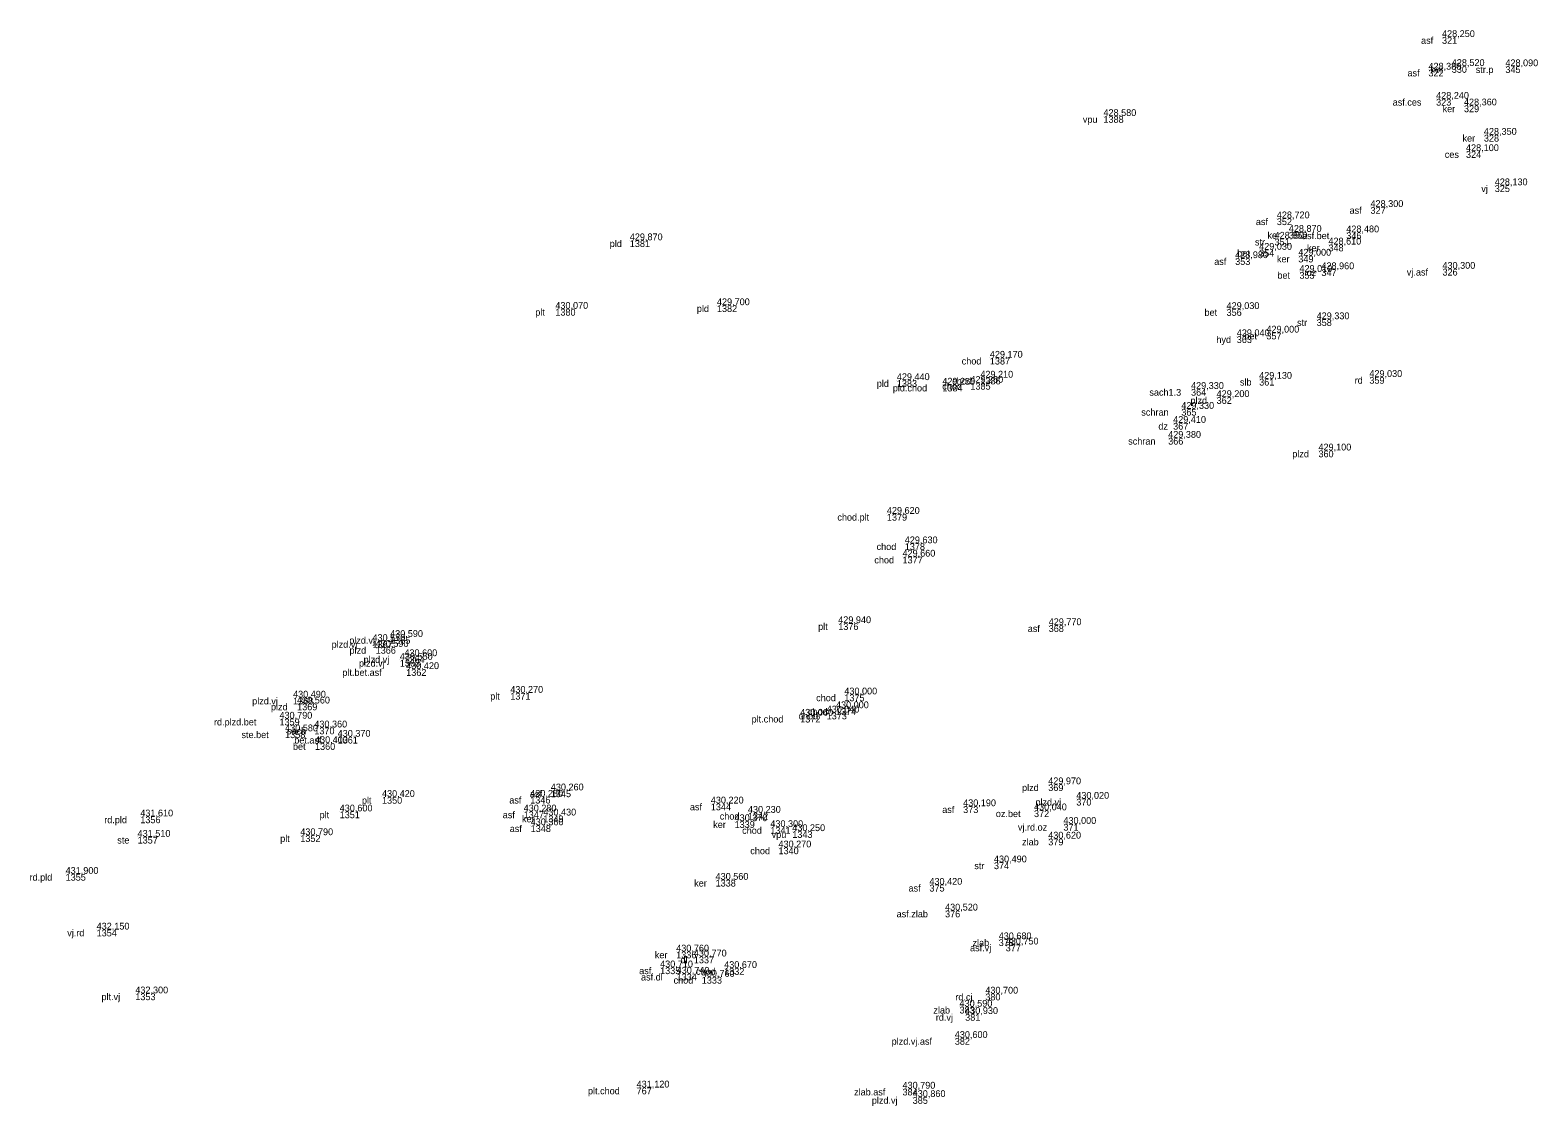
# Model space of a CAD drawing. Extents: x -747136 to -746138, y -1093274 to -1091717.
# Drawn here: x -746656.1 to -746589.5, y -1092982.2 to -1092934.6 of the extents above; entities that cross this region are included whole.
import ezdxf

# ---------------------------------------------------------------- set-up
doc = ezdxf.new("R2010")
doc.units = 0
for name, color, linetype in [('1029', 7, 'Continuous'), ('404', 7, 'Continuous'), ('424', 7, 'Continuous')]:
    doc.layers.add(name, color=color, linetype=linetype)

msp = doc.modelspace()

# ---------------------------------------------------------------- linework, layer by layer
at = {"layer": '404'}
for p, q in [((-746593.72, -1092934.95), (-746593.72, -1092934.95)), ((-746593.29, -1092936.23), (-746593.29, -1092936.23)), ((-746590.92, -1092936.24), (-746590.92, -1092936.24)), ((-746594.32, -1092936.39), (-746594.32, -1092936.39)), ((-746593.98, -1092937.68), (-746593.98, -1092937.68)), ((-746592.75, -1092937.97), (-746592.75, -1092937.97)), ((-746608.68, -1092938.44), (-746608.68, -1092938.44)), ((-746591.87, -1092939.27), (-746591.87, -1092939.27)), ((-746592.66, -1092939.99), (-746592.66, -1092939.99)), ((-746591.39, -1092941.5), (-746591.39, -1092941.5)), ((-746601.02, -1092942.96), (-746601.02, -1092942.96)), ((-746596.88, -1092942.46), (-746596.88, -1092942.46)), ((-746600.49, -1092943.56), (-746600.49, -1092943.56)), ((-746597.95, -1092943.58), (-746597.95, -1092943.58)), ((-746629.61, -1092943.93), (-746629.61, -1092943.93)), ((-746601.8, -1092944.35), (-746601.8, -1092944.35)), ((-746601.12, -1092943.86), (-746601.12, -1092943.86)), ((-746598.74, -1092944.12), (-746598.74, -1092944.12)), ((-746602.86, -1092944.72), (-746602.86, -1092944.72)), ((-746600.07, -1092944.61), (-746600.07, -1092944.61)), ((-746600.02, -1092945.33), (-746600.02, -1092945.33)), ((-746599.05, -1092945.21), (-746599.05, -1092945.21)), ((-746593.7, -1092945.19), (-746593.7, -1092945.19)), ((-746632.9, -1092946.96), (-746632.9, -1092946.96)), ((-746625.76, -1092946.8), (-746625.76, -1092946.8)), ((-746603.24, -1092946.97), (-746603.24, -1092946.97)), ((-746599.26, -1092947.42), (-746599.26, -1092947.42)), ((-746602.79, -1092948.17), (-746602.79, -1092948.17)), ((-746601.48, -1092948.01), (-746601.48, -1092948.01)), ((-746613.7, -1092949.12), (-746613.7, -1092949.12)), ((-746617.81, -1092950.11), (-746617.81, -1092950.11)), ((-746615.8, -1092950.31), (-746615.8, -1092950.31)), ((-746614.56, -1092950.23), (-746614.56, -1092950.23)), ((-746614.12, -1092950), (-746614.12, -1092950)), ((-746601.8, -1092950.05), (-746601.8, -1092950.05)), ((-746596.93, -1092949.97), (-746596.93, -1092949.97)), ((-746604.81, -1092950.5), (-746604.81, -1092950.5)), ((-746603.68, -1092950.86), (-746603.68, -1092950.86)), ((-746605.24, -1092951.38), (-746605.24, -1092951.38)), ((-746605.6, -1092952), (-746605.6, -1092952)), ((-746605.82, -1092952.66), (-746605.82, -1092952.66)), ((-746599.18, -1092953.22), (-746599.18, -1092953.22)), ((-746618.25, -1092956.02), (-746618.25, -1092956.02)), ((-746617.46, -1092957.32), (-746617.46, -1092957.32)), ((-746617.56, -1092957.91), (-746617.56, -1092957.91)), ((-746620.4, -1092960.85), (-746620.4, -1092960.85)), ((-746611.1, -1092960.94), (-746611.1, -1092960.94)), ((-746640.98, -1092961.64), (-746640.98, -1092961.64)), ((-746640.2, -1092961.46), (-746640.2, -1092961.46)), ((-746640.84, -1092961.9), (-746640.84, -1092961.9)), ((-746639.57, -1092962.31), (-746639.57, -1092962.31)), ((-746639.77, -1092962.47), (-746639.77, -1092962.47)), ((-746639.49, -1092962.88), (-746639.49, -1092962.88)), ((-746644.49, -1092964.14), (-746644.49, -1092964.14)), ((-746634.89, -1092963.93), (-746634.89, -1092963.93)), ((-746620.13, -1092964), (-746620.13, -1092964)), ((-746644.31, -1092964.4), (-746644.31, -1092964.4)), ((-746622.08, -1092964.94), (-746622.08, -1092964.94)), ((-746620.91, -1092964.8), (-746620.91, -1092964.8)), ((-746620.5, -1092964.61), (-746620.5, -1092964.61)), ((-746645.09, -1092965.07), (-746645.09, -1092965.07)), ((-746644.84, -1092965.63), (-746644.84, -1092965.63)), ((-746643.55, -1092965.46), (-746643.55, -1092965.46)), ((-746643.52, -1092966.15), (-746643.52, -1092966.15)), ((-746642.52, -1092965.87), (-746642.52, -1092965.87)), ((-746633.1, -1092968.24), (-746633.1, -1092968.24)), ((-746611.12, -1092967.97), (-746611.12, -1092967.97)), ((-746640.56, -1092968.53), (-746640.56, -1092968.53)), ((-746634.01, -1092968.52), (-746634.01, -1092968.52)), ((-746626.03, -1092968.82), (-746626.03, -1092968.82)), ((-746614.88, -1092968.94), (-746614.88, -1092968.94)), ((-746609.88, -1092968.61), (-746609.88, -1092968.61)), ((-746651.24, -1092969.39), (-746651.24, -1092969.39)), ((-746642.43, -1092969.17), (-746642.43, -1092969.17)), ((-746634.3, -1092969.17), (-746634.3, -1092969.17)), ((-746633.43, -1092969.35), (-746633.43, -1092969.35)), ((-746624.98, -1092969.6), (-746624.98, -1092969.6)), ((-746624.39, -1092969.23), (-746624.39, -1092969.23)), ((-746611.75, -1092969.12), (-746611.75, -1092969.12)), ((-746651.36, -1092970.29), (-746651.36, -1092970.29)), ((-746644.17, -1092970.22), (-746644.17, -1092970.22)), ((-746633.99, -1092969.78), (-746633.99, -1092969.78)), ((-746623.4, -1092969.86), (-746623.4, -1092969.86)), ((-746622.43, -1092970.04), (-746622.43, -1092970.04)), ((-746610.45, -1092969.72), (-746610.45, -1092969.72)), ((-746623.04, -1092970.76), (-746623.04, -1092970.76)), ((-746611.12, -1092970.37), (-746611.12, -1092970.37)), ((-746613.52, -1092971.42), (-746613.52, -1092971.42)), ((-746654.54, -1092971.93), (-746654.54, -1092971.93)), ((-746625.82, -1092972.19), (-746625.82, -1092972.19)), ((-746616.37, -1092972.41), (-746616.37, -1092972.41)), ((-746615.68, -1092973.55), (-746615.68, -1092973.55)), ((-746653.17, -1092974.39), (-746653.17, -1092974.39)), ((-746613.31, -1092974.82), (-746613.31, -1092974.82)), ((-746627.56, -1092975.36), (-746627.56, -1092975.36)), ((-746626.78, -1092975.58), (-746626.78, -1092975.58)), ((-746613, -1092975.05), (-746613, -1092975.05)), ((-746628.27, -1092976.06), (-746628.27, -1092976.06)), ((-746627.54, -1092976.34), (-746627.54, -1092976.34)), ((-746625.44, -1092976.09), (-746625.44, -1092976.09)), ((-746626.43, -1092976.48), (-746626.43, -1092976.48)), ((-746651.46, -1092977.21), (-746651.46, -1092977.21)), ((-746613.9, -1092977.22), (-746613.9, -1092977.22)), ((-746615.04, -1092977.8), (-746615.04, -1092977.8)), ((-746614.79, -1092978.12), (-746614.79, -1092978.12)), ((-746615.25, -1092979.18), (-746615.25, -1092979.18)), ((-746629.31, -1092981.37), (-746629.31, -1092981.37)), ((-746617.56, -1092981.42), (-746617.56, -1092981.42)), ((-746617.11, -1092981.79), (-746617.11, -1092981.79))]:
    msp.add_line(p, q, dxfattribs=at)

# ---------------------------------------------------------------- texts
at = {"layer": '1029'}
for s, p in [('428,250', (-746593.72, -1092934.95)), ('428,380', (-746594.32, -1092936.39)), ('428,520', (-746593.29, -1092936.23)), ('428,090', (-746590.92, -1092936.24)), ('428,240', (-746593.98, -1092937.68)), ('428,360', (-746592.75, -1092937.97)), ('428,580', (-746608.68, -1092938.44)), ('428,350', (-746591.87, -1092939.27)), ('428,100', (-746592.66, -1092939.99)), ('428,130', (-746591.39, -1092941.5)), ('428,300', (-746596.88, -1092942.46)), ('428,720', (-746601.02, -1092942.96)), ('429,870', (-746629.61, -1092943.93)), ('428,950', (-746601.12, -1092943.86)), ('428,870', (-746600.49, -1092943.56)), ('428,480', (-746597.95, -1092943.58)), ('429,030', (-746601.8, -1092944.35)), ('429,000', (-746600.07, -1092944.61)), ('428,610', (-746598.74, -1092944.12)), ('428,980', (-746602.86, -1092944.72)), ('429,010', (-746600.02, -1092945.33)), ('428,960', (-746599.05, -1092945.21)), ('430,300', (-746593.7, -1092945.19)), ('430,070', (-746632.9, -1092946.96)), ('429,700', (-746625.76, -1092946.8)), ('429,030', (-746603.24, -1092946.97)), ('429,000', (-746601.48, -1092948.01)), ('429,330', (-746599.26, -1092947.42)), ('429,040', (-746602.79, -1092948.17)), ('429,170', (-746613.7, -1092949.12)), ('429,210', (-746614.12, -1092950)), ('429,030', (-746596.93, -1092949.97)), ('429,440', (-746617.81, -1092950.11)), ('429,250', (-746615.8, -1092950.31)), ('429,260', (-746614.56, -1092950.23)), ('429,330', (-746604.81, -1092950.5)), ('429,130', (-746601.8, -1092950.05)), ('429,200', (-746603.68, -1092950.86)), ('429,410', (-746605.6, -1092952)), ('429,330', (-746605.24, -1092951.38)), ('429,380', (-746605.82, -1092952.66)), ('429,100', (-746599.18, -1092953.22)), ('429,620', (-746618.25, -1092956.02)), ('429,630', (-746617.46, -1092957.32)), ('429,660', (-746617.56, -1092957.91)), ('429,940', (-746620.4, -1092960.85)), ('429,770', (-746611.1, -1092960.94)), ('430,570', (-746640.98, -1092961.64)), ('430,590', (-746640.84, -1092961.9)), ('430,590', (-746640.2, -1092961.46)), ('430,550', (-746639.77, -1092962.47)), ('430,600', (-746639.57, -1092962.31)), ('430,420', (-746639.49, -1092962.88)), ('430,270', (-746634.89, -1092963.93)), ('430,000', (-746620.13, -1092964)), ('430,490', (-746644.49, -1092964.14)), ('430,560', (-746644.31, -1092964.4)), ('430,000', (-746620.5, -1092964.61)), ('430,790', (-746645.09, -1092965.07)), ('430,060', (-746622.08, -1092964.94)), ('430,040', (-746620.91, -1092964.8)), ('430,580', (-746644.84, -1092965.63)), ('430,360', (-746643.55, -1092965.46)), ('430,370', (-746642.52, -1092965.87)), ('430,400', (-746643.52, -1092966.15)), ('429,970', (-746611.12, -1092967.97)), ('430,420', (-746640.56, -1092968.53)), ('430,280', (-746634.01, -1092968.52)), ('430,260', (-746633.1, -1092968.24)), ('430,020', (-746609.88, -1092968.61)), ('430,600', (-746642.43, -1092969.17)), ('430,280', (-746634.3, -1092969.17)), ('430,220', (-746626.03, -1092968.82)), ('430,230', (-746624.39, -1092969.23)), ('430,190', (-746614.88, -1092968.94)), ('430,040', (-746611.75, -1092969.12)), ('431,610', (-746651.24, -1092969.39)), ('430,360', (-746633.99, -1092969.78)), ('430,430', (-746633.43, -1092969.35)), ('430,370', (-746624.98, -1092969.6)), ('430,300', (-746623.4, -1092969.86)), ('430,000', (-746610.45, -1092969.72)), ('431,510', (-746651.36, -1092970.29)), ('430,790', (-746644.17, -1092970.22)), ('430,250', (-746622.43, -1092970.04)), ('430,620', (-746611.12, -1092970.37)), ('430,270', (-746623.04, -1092970.76)), ('431,900', (-746654.54, -1092971.93)), ('430,490', (-746613.52, -1092971.42)), ('430,560', (-746625.82, -1092972.19)), ('430,420', (-746616.37, -1092972.41)), ('430,520', (-746615.68, -1092973.55)), ('432,150', (-746653.17, -1092974.39)), ('430,680', (-746613.31, -1092974.82)), ('430,750', (-746613, -1092975.05)), ('430,760', (-746627.56, -1092975.36)), ('430,770', (-746626.78, -1092975.58)), ('430,710', (-746628.27, -1092976.06)), ('430,740', (-746627.54, -1092976.34)), ('430,760', (-746626.43, -1092976.48)), ('430,670', (-746625.44, -1092976.09)), ('432,300', (-746651.46, -1092977.21)), ('430,700', (-746613.9, -1092977.22)), ('430,590', (-746615.04, -1092977.8)), ('430,930', (-746614.79, -1092978.12)), ('430,600', (-746615.25, -1092979.18)), ('431,120', (-746629.31, -1092981.37)), ('430,790', (-746617.56, -1092981.42)), ('430,860', (-746617.11, -1092981.79))]:
    msp.add_text(s, height=0.3, dxfattribs=at).set_placement(p)
at = {"layer": '424'}
for s, p in [(' asf', (-746594.757, -1092935.25)), ('321', (-746593.72, -1092935.25)), (' asf', (-746595.357, -1092936.69)), (' ker', (-746594.346, -1092936.53)), ('330', (-746593.29, -1092936.53)), (' str.p', (-746592.339, -1092936.54)), ('345', (-746590.92, -1092936.54)), ('322', (-746594.32, -1092936.69)), (' asf.ces', (-746596.011, -1092937.98)), ('323', (-746593.98, -1092937.98)), (' ker', (-746593.806, -1092938.27)), ('329', (-746592.75, -1092938.27)), (' vpu', (-746609.703, -1092938.74)), ('1388', (-746608.68, -1092938.74)), (' ker', (-746592.926, -1092939.57)), ('328', (-746591.87, -1092939.57)), (' ces', (-746593.709, -1092940.29)), ('324', (-746592.66, -1092940.29)), (' vj', (-746592.094, -1092941.8)), ('325', (-746591.39, -1092941.8)), (' asf', (-746602.057, -1092943.26)), ('352', (-746601.02, -1092943.26)), (' asf', (-746597.917, -1092942.76)), ('327', (-746596.88, -1092942.76)), (' ker', (-746601.546, -1092943.86)), ('350', (-746600.49, -1092943.86)), (' asf.bet', (-746600.019, -1092943.88)), ('346', (-746597.95, -1092943.88)), (' pld', (-746630.609, -1092944.23)), ('1381', (-746629.61, -1092944.23)), (' bet', (-746602.886, -1092944.65)), (' str', (-746602.098, -1092944.16)), ('354', (-746601.8, -1092944.65)), ('351', (-746601.12, -1092944.16)), (' ker', (-746599.796, -1092944.42)), ('348', (-746598.74, -1092944.42)), (' asf', (-746603.897, -1092945.02)), ('353', (-746602.86, -1092945.02)), (' ker', (-746601.126, -1092944.91)), ('349', (-746600.07, -1092944.91)), (' bet', (-746601.106, -1092945.63)), ('355', (-746600.02, -1092945.63)), (' oz', (-746599.815, -1092945.51)), ('347', (-746599.05, -1092945.51)), (' vj.asf', (-746595.386, -1092945.49)), ('326', (-746593.7, -1092945.49)), (' plt', (-746633.899, -1092947.26)), ('1380', (-746632.9, -1092947.26)), (' pld', (-746626.759, -1092947.1)), ('1382', (-746625.76, -1092947.1)), (' bet', (-746604.326, -1092947.27)), ('356', (-746603.24, -1092947.27)), (' str', (-746600.238, -1092947.72)), ('358', (-746599.26, -1092947.72)), (' hyd', (-746603.801, -1092948.47)), ('363', (-746602.79, -1092948.47)), (' bet', (-746602.566, -1092948.31)), ('357', (-746601.48, -1092948.31)), (' chod', (-746615.056, -1092949.42)), ('1387', (-746613.7, -1092949.42)), (' pld', (-746618.809, -1092950.41)), (' pld.chod', (-746618.1, -1092950.61)), ('1383', (-746617.81, -1092950.41)), (' chod', (-746615.916, -1092950.53)), ('1384', (-746615.8, -1092950.61)), (' chod', (-746615.476, -1092950.3)), ('1385', (-746614.56, -1092950.53)), ('1386', (-746614.12, -1092950.3)), (' slb', (-746602.761, -1092950.35)), ('361', (-746601.8, -1092950.35)), (' rd', (-746597.691, -1092950.27)), ('359', (-746596.93, -1092950.27)), (' sach1.3', (-746606.763, -1092950.8)), (' plzd', (-746604.948, -1092951.16)), ('364', (-746604.81, -1092950.8)), ('362', (-746603.68, -1092951.16)), (' schran', (-746607.118, -1092951.68)), ('365', (-746605.24, -1092951.68)), (' dz', (-746606.365, -1092952.3)), ('367', (-746605.6, -1092952.3)), (' schran', (-746607.698, -1092952.96)), ('366', (-746605.82, -1092952.96)), (' plzd', (-746600.448, -1092953.52)), ('360', (-746599.18, -1092953.52)), (' chod.plt', (-746620.55, -1092956.32)), ('1379', (-746618.25, -1092956.32)), (' chod', (-746618.816, -1092957.62)), ('1378', (-746617.46, -1092957.62)), (' chod', (-746618.916, -1092958.21)), ('1377', (-746617.56, -1092958.21)), (' plt', (-746621.399, -1092961.15)), ('1376', (-746620.4, -1092961.15)), (' asf', (-746612.137, -1092961.24)), ('368', (-746611.1, -1092961.24)), (' plzd.vj', (-746642.898, -1092961.94)), (' plzd.vj', (-746642.118, -1092961.76)), ('1367', (-746640.98, -1092961.94)), ('1365', (-746640.2, -1092961.76)), (' plzd', (-746642.108, -1092962.2)), (' plzd.vj', (-746641.488, -1092962.61)), ('1366', (-746640.84, -1092962.2)), ('1364', (-746639.57, -1092962.61)), (' plt.bet.asf', (-746642.423, -1092963.18)), (' plzd.vj', (-746641.688, -1092962.77)), ('1363', (-746639.77, -1092962.77)), ('1362', (-746639.49, -1092963.18)), (' plzd.vj', (-746646.408, -1092964.44)), ('1368', (-746644.49, -1092964.44)), (' plt', (-746635.889, -1092964.23)), ('1371', (-746634.89, -1092964.23)), (' chod', (-746621.486, -1092964.3)), ('1375', (-746620.13, -1092964.3)), (' plzd', (-746645.578, -1092964.7)), ('1369', (-746644.31, -1092964.7)), (' plt.chod', (-746624.34, -1092965.24)), (' chod', (-746622.266, -1092965.1)), ('1372', (-746622.08, -1092965.24)), (' chod', (-746621.856, -1092964.91)), ('1373', (-746620.91, -1092965.1)), ('1374', (-746620.5, -1092964.91)), (' rd.plzd.bet', (-746648.096, -1092965.37)), (' ste.bet', (-746646.881, -1092965.93)), ('1359', (-746645.09, -1092965.37)), ('1358', (-746644.84, -1092965.93)), (' sach', (-746644.868, -1092965.76)), ('1370', (-746643.55, -1092965.76)), (' bet', (-746644.606, -1092966.45)), (' bet.asf', (-746644.549, -1092966.17)), ('1360', (-746643.52, -1092966.45)), ('1361', (-746642.52, -1092966.17)), (' asf', (-746634.137, -1092968.54)), ('1345', (-746633.1, -1092968.54)), (' plzd', (-746612.388, -1092968.27)), ('369', (-746611.12, -1092968.27)), (' plt', (-746641.559, -1092968.83)), ('1350', (-746640.56, -1092968.83)), (' asf', (-746635.047, -1092968.82)), ('1346', (-746634.01, -1092968.82)), (' asf', (-746627.067, -1092969.12)), ('1344', (-746626.03, -1092969.12)), (' asf', (-746615.917, -1092969.24)), ('373', (-746614.88, -1092969.24)), (' plzd.vj', (-746611.798, -1092968.91)), ('370', (-746609.88, -1092968.91)), (' rd.pld', (-746652.945, -1092969.69)), ('1356', (-746651.24, -1092969.69)), (' plt', (-746643.429, -1092969.47)), ('1351', (-746642.43, -1092969.47)), (' asf', (-746635.337, -1092969.47)), (' ker', (-746634.486, -1092969.65)), ('1347', (-746634.3, -1092969.47)), ('1349', (-746633.43, -1092969.65)), (' ker', (-746626.036, -1092969.9)), (' chod', (-746625.746, -1092969.53)), ('1339', (-746624.98, -1092969.9)), ('1342', (-746624.39, -1092969.53)), (' oz.bet', (-746613.547, -1092969.42)), ('372', (-746611.75, -1092969.42)), (' ste', (-746652.369, -1092970.59)), ('1357', (-746651.36, -1092970.59)), (' plt', (-746645.169, -1092970.52)), ('1352', (-746644.17, -1092970.52)), (' asf', (-746635.027, -1092970.08)), ('1348', (-746633.99, -1092970.08)), (' chod', (-746624.756, -1092970.16)), ('1341', (-746623.4, -1092970.16)), (' vpu', (-746623.453, -1092970.34)), ('1343', (-746622.43, -1092970.34)), (' vj.rd.oz', (-746612.571, -1092970.02)), (' zlab', (-746612.388, -1092970.67)), ('371', (-746610.45, -1092970.02)), (' chod', (-746624.396, -1092971.06)), ('1340', (-746623.04, -1092971.06)), ('379', (-746611.12, -1092970.67)), (' str', (-746614.498, -1092971.72)), ('374', (-746613.52, -1092971.72)), (' rd.pld', (-746656.245, -1092972.23)), ('1355', (-746654.54, -1092972.23)), (' ker', (-746626.876, -1092972.49)), ('1338', (-746625.82, -1092972.49)), (' asf', (-746617.407, -1092972.71)), ('375', (-746616.37, -1092972.71)), (' asf.zlab', (-746617.931, -1092973.85)), ('376', (-746615.68, -1092973.85)), (' vj.rd', (-746654.58, -1092974.69)), ('1354', (-746653.17, -1092974.69)), (' zlab', (-746614.578, -1092975.12)), ('378', (-746613.31, -1092975.12)), (' ker', (-746628.616, -1092975.66)), ('1336', (-746627.56, -1092975.66)), (' dl', (-746627.484, -1092975.88)), ('1337', (-746626.78, -1092975.88)), (' asf.vj', (-746614.686, -1092975.35)), ('377', (-746613, -1092975.35)), (' asf', (-746629.307, -1092976.36)), (' asf.dl', (-746629.226, -1092976.64)), ('1335', (-746628.27, -1092976.36)), ('1334', (-746627.54, -1092976.64)), (' chod', (-746626.796, -1092976.39)), ('1332', (-746625.44, -1092976.39)), (' chod', (-746627.786, -1092976.78)), ('1333', (-746626.43, -1092976.78)), (' plt.vj', (-746653.068, -1092977.51)), ('1353', (-746651.46, -1092977.51)), (' rd.cj', (-746615.336, -1092977.52)), ('380', (-746613.9, -1092977.52)), (' zlab', (-746616.308, -1092978.1)), (' rd.vj', (-746616.2, -1092978.42)), ('383', (-746615.04, -1092978.1)), ('381', (-746614.79, -1092978.42)), (' plzd.vj.asf', (-746618.15, -1092979.48)), ('382', (-746615.25, -1092979.48)), (' plt.chod', (-746631.57, -1092981.67)), ('767', (-746629.31, -1092981.67)), (' zlab.asf', (-746619.811, -1092981.72)), ('384', (-746617.56, -1092981.72)), (' plzd.vj', (-746619.028, -1092982.09)), ('385', (-746617.11, -1092982.09))]:
    msp.add_text(s, height=0.3, dxfattribs=at).set_placement(p)

doc.saveas('drawing.dxf')
